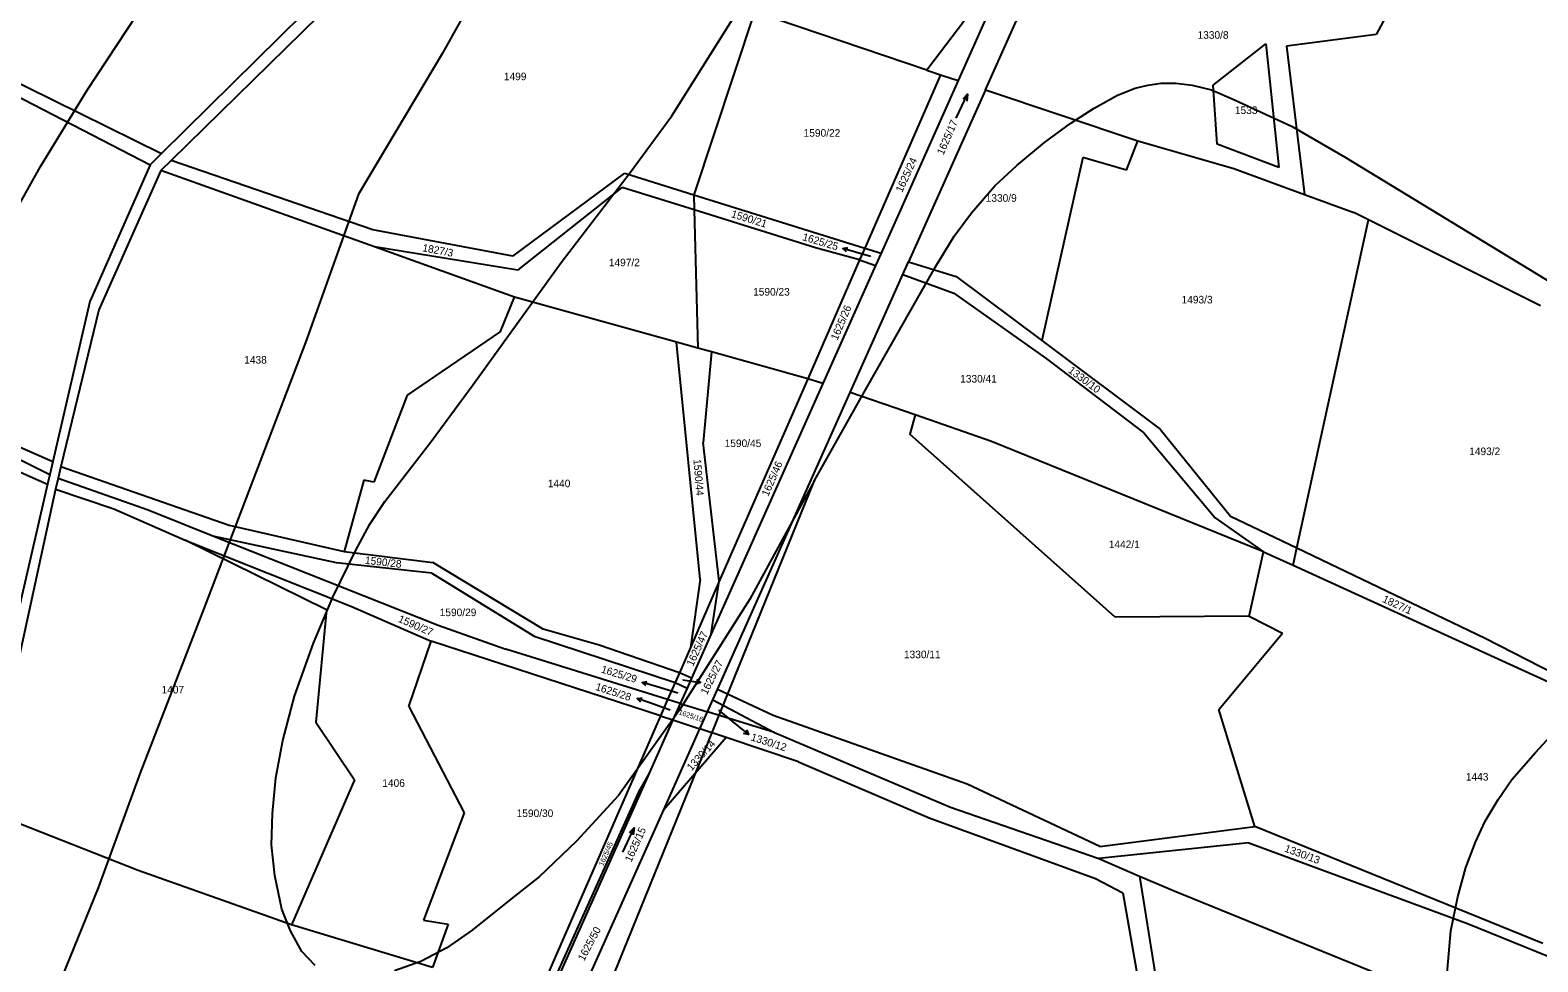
# Model space of a CAD drawing. Extents: x -546762 to -540209, y -1046851 to -1035694.
# Drawn here: x -543306.6 to -542968.6, y -1041200.9 to -1040992 of the extents above; entities that cross this region are included whole.
import ezdxf

# ---------------------------------------------------------------- set-up
doc = ezdxf.new("R2010")
doc.units = 0
for name, color, linetype in [('Vrstva 1', 7, 'Continuous'), ('Vrstva 16', 7, 'Continuous'), ('Vrstva 18', 7, 'Continuous'), ('Vrstva 25', 7, 'Continuous'), ('Vrstva 52', 7, 'Continuous'), ('Vrstva 6', 7, 'Continuous')]:
    doc.layers.add(name, color=color, linetype=linetype)

msp = doc.modelspace()

# ---------------------------------------------------------------- linework, layer by layer
at = {"layer": 'Vrstva 1'}
for points in [[(-543069.18, -1040937.44), (-543098.59, -1041003.36)], [(-543092.45, -1041005.44), (-543063.14, -1040939.88)], [(-543092.78, -1040984.15), (-543105.62, -1041000.99)], [(-543102.54, -1041002.03), (-543119.51, -1041040.89)], [(-543105.62, -1041000.99), (-543102.54, -1041002.03)], [(-543098.59, -1041003.36), (-543115.84, -1041042.03)], [(-543092.45, -1041005.44), (-543109.67, -1041043.95)], [(-543120.68, -1041043.57), (-543132.3, -1041070.19)], [(-543119.51, -1041040.89), (-543120.68, -1041043.57)], [(-543115.84, -1041042.03), (-543117.07, -1041044.78)], [(-543117.07, -1041044.78), (-543128.89, -1041071.29)], [(-543122.77, -1041073.26), (-543110.95, -1041046.82)], [(-543110.95, -1041046.82), (-543109.67, -1041043.95)], [(-543132.3, -1041070.19), (-543152.12, -1041115.59)], [(-543128.89, -1041071.29), (-543153.91, -1041127.39)], [(-543152.54, -1041139.88), (-543122.77, -1041073.26)], [(-543152.12, -1041115.59), (-543158.6, -1041130.42)], [(-543153.91, -1041127.39), (-543158.34, -1041137.32)], [(-543158.6, -1041130.42), (-543161.08, -1041136.11)], [(-543161.08, -1041136.11), (-543162.04, -1041138.3)], [(-543158.34, -1041137.32), (-543159.34, -1041139.55)], [(-543162.04, -1041138.3), (-543163.7, -1041142.11)], [(-543159.34, -1041139.55), (-543160.87, -1041142.99)], [(-543153.58, -1041142.21), (-543152.54, -1041139.88)], [(-543163.7, -1041142.11), (-543165.29, -1041145.76)], [(-543160.87, -1041142.99), (-543162.52, -1041146.69)], [(-543160.87, -1041142.99), (-543154.77, -1041144.88)], [(-543156.48, -1041148.71), (-543154.77, -1041144.88)], [(-543154.77, -1041144.88), (-543153.58, -1041142.21)], [(-543165.29, -1041145.76), (-543193.04, -1041209.32)], [(-543162.52, -1041146.69), (-543167.84, -1041158.61)], [(-543162.52, -1041146.69), (-543156.48, -1041148.71)], [(-543164.59, -1041166.87), (-543156.48, -1041148.71)], [(-543167.84, -1041158.61), (-543190.89, -1041210.3)], [(-543184.13, -1041210.58), (-543164.59, -1041166.87)]]:
    msp.add_lwpolyline(points, dxfattribs=at)
at = {"layer": 'Vrstva 16'}
for p, q in [((-543121.55, -1041041.83), (-543124.43, -1041040.99)), ((-543166.52, -1041139.15), (-543169.39, -1041138.28)), ((-543159.31, -1041137.88), (-543156.34, -1041138.28)), ((-543167.7, -1041142.88), (-543170.53, -1041141.89)), ((-543147.9, -1041148.06), (-543145.57, -1041149.95))]:
    msp.add_line(p, q, dxfattribs=at)
for points in [[(-543123.61, -1041041.75), (-543124.43, -1041040.99), (-543123.33, -1041040.79)], [(-543118.23, -1041042.8), (-543121.55, -1041041.83)], [(-543168.58, -1041139.05), (-543169.39, -1041138.28), (-543168.29, -1041138.09)], [(-543160.31, -1041137.74), (-543159.31, -1041137.88)], [(-543157.26, -1041137.65), (-543156.34, -1041138.28), (-543157.4, -1041138.64)], [(-543161.45, -1041140.69), (-543166.52, -1041139.15)], [(-543169.75, -1041142.69), (-543170.53, -1041141.89), (-543169.42, -1041141.75)], [(-543163.13, -1041144.48), (-543167.7, -1041142.88)], [(-543152.31, -1041144.48), (-543147.9, -1041148.06)], [(-543146.03, -1041148.93), (-543145.57, -1041149.95), (-543146.66, -1041149.71)]]:
    msp.add_lwpolyline(points, dxfattribs=at)
at = {"layer": 'Vrstva 25'}
for points in [[(-543099.02, -1041011.8), (-543096.46, -1041006.36), (-543097.55, -1041007.51)], [(-543096.46, -1041006.36), (-543096.65, -1041007.94)], [(-543173.72, -1041176.33), (-543171.24, -1041170.87), (-543172.31, -1041172.03)], [(-543171.24, -1041170.87), (-543171.4, -1041172.44)]]:
    msp.add_lwpolyline(points, dxfattribs=at)
at = {"layer": 'Vrstva 52'}
for points in [[(-543114.91, -1040780.64), (-543113, -1040792.52), (-543112.57, -1040803.33), (-543112.79, -1040813.08), (-543114.48, -1040823.69), (-543117.02, -1040834.08), (-543121.05, -1040844.04), (-543127.62, -1040856.34), (-543132.71, -1040864.4), (-543140.55, -1040877.5), (-543166.14, -1040918.69), (-543197.89, -1040967.9), (-543214.21, -1040997.22), (-543233.03, -1041028.81), (-543244.9, -1041062.1), (-543267.79, -1041121.9), (-543281.99, -1041158.59), (-543291.42, -1041184.35), (-543299.54, -1041204.34), (-543308.14, -1041219.86)], [(-543322.15, -1041054.55), (-543304.35, -1041022.63), (-543293.87, -1041005.52), (-543253.63, -1040944.47), (-543217.93, -1040882.13), (-543193.27, -1040831.47), (-543168.15, -1040787.72)], [(-543242.71, -1041201.78), (-543245.74, -1041198.58), (-543248.28, -1041193.97), (-543250.22, -1041189.12), (-543251.79, -1041181.61), (-543252.52, -1041174.7), (-543252.28, -1041167.68), (-543251.55, -1041159.68), (-543249.97, -1041151.32), (-543247.35, -1041141.35), (-543243.11, -1041129.48), (-543238.75, -1041119.18), (-543233.66, -1041108.76), (-543230.51, -1041102.82), (-543227.12, -1041097.73), (-543216.74, -1041084.25), (-543207.31, -1041071.47), (-543187.6, -1041044.12), (-543172.13, -1041023.97), (-543162.8, -1041011.25), (-543101.67, -1040914.04)], [(-543130.8, -1041093.03), (-543119.35, -1041072.67), (-543103.67, -1041045.1), (-543099.43, -1041038.23), (-543095.55, -1041033.02), (-543090.35, -1041026.96), (-543085.38, -1041022.35), (-543079.2, -1041017.26), (-543073.27, -1041012.9), (-543068.06, -1041009.51), (-543062.86, -1041006.6), (-543058.86, -1041005.08), (-543056.02, -1041004.38), (-543053.05, -1041003.9), (-543049.79, -1041003.9), (-543046.13, -1041004.38)], [(-543046.13, -1041004.38), (-543041.77, -1041005.42), (-543036.64, -1041007.64), (-543023.7, -1041013.66), (-543011.94, -1041020.45), (-542939.35, -1041064.58)], [(-543367.43, -1041496.06), (-543358.52, -1041484.25), (-543291.66, -1041388.79), (-543235.84, -1041305.67), (-543212.48, -1041277.09), (-543186.52, -1041230.33), (-543130.8, -1041093.03)], [(-543130.8, -1041093.03), (-543145.27, -1041119.62), (-543161.13, -1041144.58), (-543174.7, -1041163.61), (-543184.14, -1041173.91), (-543192.53, -1041181.84), (-543198.49, -1041186.61), (-543207.55, -1041193.82), (-543213.23, -1041197.83), (-543219.04, -1041200.88), (-543224.92, -1041202.96)], [(-542956.93, -1041259.59), (-542974.13, -1041243.84), (-542981.46, -1041235.66), (-542985.09, -1041229.36), (-542987.51, -1041223.18), (-542988.84, -1041217.12), (-542989.21, -1041210.21), (-542988.84, -1041202.58), (-542988.12, -1041193.98), (-542986.54, -1041186.34), (-542984.73, -1041179.8), (-542982.55, -1041174.11), (-542980.37, -1041169.38), (-542977.46, -1041164.53), (-542974.43, -1041160.05), (-542969.1, -1041153.99), (-542964.14, -1041148.54)]]:
    msp.add_lwpolyline(points, dxfattribs=at)
at = {"layer": 'Vrstva 6'}
for points in [[(-543218.98, -1040962.2), (-543277.16, -1041019.66)], [(-543216.26, -1040963.63), (-543275.01, -1041021.25)], [(-542995.48, -1040975.63), (-543004.84, -1040993.04)], [(-543144.2, -1040987.96), (-543157.86, -1041028.95)], [(-543105.62, -1041000.99), (-543144.2, -1040987.96)], [(-543041.39, -1041004.41), (-543029.59, -1040995.11)], [(-543029.59, -1040995.11), (-543026.68, -1041022.85)], [(-543004.84, -1040993.04), (-543024.91, -1040995.62)], [(-543024.91, -1040995.62), (-543020.9, -1041028.86)], [(-543313.56, -1041001.76), (-543277.16, -1041019.66)], [(-543102.54, -1041002.03), (-543098.59, -1041003.36)], [(-543316.78, -1041003.12), (-543279.73, -1041022.2)], [(-543092.45, -1041005.44), (-543058.28, -1041016.82)], [(-543040.52, -1041017.59), (-543041.39, -1041004.41)], [(-543277.16, -1041019.66), (-543279.73, -1041022.2)], [(-543060.81, -1041023.41), (-543058.28, -1041016.82)], [(-543058.28, -1041016.82), (-543036.78, -1041023.06)], [(-543026.68, -1041022.85), (-543040.52, -1041017.59)], [(-543279.73, -1041022.2), (-543293.27, -1041052.9)], [(-543275.01, -1041021.25), (-543277.31, -1041023.51)], [(-543229.84, -1041036.82), (-543275.01, -1041021.25)], [(-543070.58, -1041020.61), (-543079.84, -1041061.62)], [(-543060.81, -1041023.41), (-543070.58, -1041020.61)], [(-543036.78, -1041023.06), (-543020.9, -1041028.86)], [(-543277.31, -1041023.51), (-543291.23, -1041054.72)], [(-543229.42, -1041040.65), (-543277.31, -1041023.51)], [(-543198.43, -1041042.68), (-543173.3, -1041024.14)], [(-543173.3, -1041024.14), (-543157.86, -1041028.95)], [(-543197.32, -1041045.83), (-543173.92, -1041027.33)], [(-543157.77, -1041032.36), (-543173.92, -1041027.33)], [(-543157.86, -1041028.95), (-543119.51, -1041040.89)], [(-543157.86, -1041028.95), (-543157.77, -1041032.36)], [(-543020.9, -1041028.86), (-543009.82, -1041032.91)], [(-543130.58, -1041040.84), (-543157.77, -1041032.36)], [(-543157.77, -1041032.36), (-543156.96, -1041063.32)], [(-543006.53, -1041034.56), (-543009.82, -1041032.91)], [(-543198.43, -1041042.68), (-543229.84, -1041036.82)], [(-543022.63, -1041108.14), (-543006.53, -1041034.56)], [(-542968.01, -1041053.85), (-543006.53, -1041034.56)], [(-543197.32, -1041045.83), (-543229.42, -1041040.65)], [(-543198.07, -1041051.87), (-543229.42, -1041040.65)], [(-543120.68, -1041043.57), (-543130.58, -1041040.84)], [(-543120.68, -1041043.57), (-543117.07, -1041044.78)], [(-543119.51, -1041040.89), (-543115.84, -1041042.03)], [(-543110.95, -1041046.82), (-543099.57, -1041051.02)], [(-543109.67, -1041043.95), (-543099.04, -1041047.26)], [(-543099.04, -1041047.26), (-543079.84, -1041061.62)], [(-543293.27, -1041052.9), (-543301.55, -1041088.72)], [(-543201.21, -1041059.59), (-543198.07, -1041051.87)], [(-543161.73, -1041061.99), (-543198.07, -1041051.87)], [(-543099.57, -1041051.02), (-543078.82, -1041065.68)], [(-543291.23, -1041054.72), (-543299.74, -1041089.88)], [(-543201.21, -1041059.59), (-543222.13, -1041073.87)], [(-543156.96, -1041063.32), (-543161.73, -1041061.99)], [(-543156.42, -1041115.22), (-543161.73, -1041061.99)], [(-543153.88, -1041064.18), (-543156.96, -1041063.32)], [(-543079.84, -1041061.62), (-543053.24, -1041081.52)], [(-543153.88, -1041064.18), (-543155.71, -1041084.48)], [(-543132.3, -1041070.19), (-543153.88, -1041064.18)], [(-543078.82, -1041065.68), (-543056.96, -1041082.3)], [(-543128.89, -1041071.29), (-543132.3, -1041070.19)], [(-543222.13, -1041073.87), (-543229.57, -1041093.42)], [(-543108.24, -1041078.31), (-543122.77, -1041073.26)], [(-543333.32, -1041080.3), (-543302.74, -1041093.86)], [(-543108.24, -1041078.31), (-543109.42, -1041082.59)], [(-543091.12, -1041084.26), (-543108.24, -1041078.31)], [(-543320.16, -1041082.74), (-543302.24, -1041091.7)], [(-543315.88, -1041082.44), (-543301.55, -1041088.72)], [(-543063.35, -1041123.65), (-543109.42, -1041082.59)], [(-543056.96, -1041082.3), (-543040.91, -1041101.42)], [(-543053.24, -1041081.52), (-543037.48, -1041101.03)], [(-543152.12, -1041115.59), (-543155.71, -1041084.48)], [(-543030.08, -1041108.99), (-543091.12, -1041084.26)], [(-543301.55, -1041088.72), (-543302.24, -1041091.7)], [(-543299.74, -1041089.88), (-543300.38, -1041092.51)], [(-543299.74, -1041089.88), (-543262.03, -1041103)], [(-543302.74, -1041093.86), (-543319.4, -1041166)], [(-543302.24, -1041091.7), (-543302.74, -1041093.86)], [(-543300.38, -1041092.51), (-543300.97, -1041094.95)], [(-543300.38, -1041092.51), (-543280.19, -1041099.62)], [(-543231.86, -1041092.94), (-543236.22, -1041108.93)], [(-543229.57, -1041093.42), (-543231.86, -1041092.94)], [(-543300.97, -1041094.95), (-543316.64, -1041167.03)], [(-543300.97, -1041094.95), (-543287.86, -1041099.37)], [(-543287.86, -1041099.37), (-543271.9, -1041106.42)], [(-543280.19, -1041099.62), (-543265.31, -1041105.54)], [(-543037.48, -1041101.03), (-543022.63, -1041108.14)], [(-543262.03, -1041103), (-543236.22, -1041108.93)], [(-543040.91, -1041101.42), (-543030.08, -1041108.99)], [(-543271.9, -1041106.42), (-543234.77, -1041121.19)], [(-543240.23, -1041121.98), (-543271.9, -1041106.42)], [(-543265.31, -1041105.54), (-543215.19, -1041125.46)], [(-543237.98, -1041111.45), (-543265.31, -1041105.54)], [(-543236.22, -1041108.93), (-543216.34, -1041111.38)], [(-543033.34, -1041123.44), (-543030.08, -1041108.99)], [(-543030.08, -1041108.99), (-543023.47, -1041112.01)], [(-543023.47, -1041112.01), (-543022.63, -1041108.14)], [(-543022.63, -1041108.14), (-542980.42, -1041128.34)], [(-543216.57, -1041113.79), (-543237.98, -1041111.45)], [(-543216.57, -1041113.79), (-543193.62, -1041127.95)], [(-543191.65, -1041126.38), (-543216.34, -1041111.38)], [(-543023.47, -1041112.01), (-542960.13, -1041140.93)], [(-543156.42, -1041115.22), (-543158.6, -1041130.42)], [(-543153.91, -1041127.39), (-543152.12, -1041115.59)], [(-543234.77, -1041121.19), (-543216.73, -1041129.07)], [(-543240.23, -1041121.98), (-543242.61, -1041147.19)], [(-543033.34, -1041123.44), (-543063.35, -1041123.65)], [(-543033.34, -1041123.44), (-543025.86, -1041127.26)], [(-543215.19, -1041125.46), (-543200, -1041130.86)], [(-543193.62, -1041127.95), (-543162.04, -1041138.3)], [(-543179.04, -1041129.96), (-543191.65, -1041126.38)], [(-543040.14, -1041144.38), (-543025.86, -1041127.26)], [(-543221.72, -1041143.67), (-543216.73, -1041129.07)], [(-543165.29, -1041145.76), (-543216.73, -1041129.07)], [(-543163.7, -1041142.11), (-543200, -1041130.86)], [(-543161.08, -1041136.11), (-543179.04, -1041129.96)], [(-542980.42, -1041128.34), (-542955.45, -1041141.18)], [(-543158.34, -1041137.32), (-543161.08, -1041136.11)], [(-543162.04, -1041138.3), (-543159.34, -1041139.55)], [(-543140.05, -1041145.67), (-543152.54, -1041139.88)], [(-543221.72, -1041143.67), (-543209.34, -1041167.5)], [(-543160.87, -1041142.99), (-543163.7, -1041142.11)], [(-543139.76, -1041149.53), (-543154.77, -1041144.88)], [(-543153.58, -1041142.21), (-543139.76, -1041149.53)], [(-543032.07, -1041170.61), (-543040.14, -1041144.38)], [(-543242.61, -1041147.19), (-543233.92, -1041160.09)], [(-543165.29, -1041145.76), (-543162.52, -1041146.69)], [(-543096.55, -1041161.08), (-543140.05, -1041145.67)], [(-543150.61, -1041150.67), (-543164.59, -1041166.87)], [(-543150.61, -1041150.67), (-543156.48, -1041148.71)], [(-543134.39, -1041156.1), (-543150.61, -1041150.67)], [(-543139.76, -1041149.53), (-543100.27, -1041166.28)], [(-543134.39, -1041156.1), (-543105.09, -1041168.61)], [(-543233.92, -1041160.09), (-543248.03, -1041192.61)], [(-543167.84, -1041158.61), (-543169.83, -1041162.2)], [(-543066.8, -1041175.11), (-543096.55, -1041161.08)], [(-543191.39, -1041210.07), (-543169.83, -1041162.2)], [(-543282.45, -1041180.49), (-543316.64, -1041167.03)], [(-543209.34, -1041167.5), (-543218.42, -1041191.58)], [(-543105.09, -1041168.61), (-543067.76, -1041182.24)], [(-543100.27, -1041166.28), (-543067.02, -1041177.8)], [(-543066.8, -1041175.11), (-543032.07, -1041170.61)], [(-542967.46, -1041196.84), (-543032.07, -1041170.61)], [(-543033.42, -1041174.28), (-543067.02, -1041177.8)], [(-543033.42, -1041174.28), (-542984.39, -1041192.33)], [(-543067.02, -1041177.8), (-543057.87, -1041181.7)], [(-543248.03, -1041192.61), (-543282.45, -1041180.49)], [(-543057.87, -1041181.7), (-543050.12, -1041185)], [(-543057.87, -1041181.7), (-543052.08, -1041218.19)], [(-543067.76, -1041182.24), (-543061.66, -1041185.46)], [(-543061.66, -1041185.46), (-543055.83, -1041218.69)], [(-543050.12, -1041185), (-543004.26, -1041203.7)], [(-543218.42, -1041191.58), (-543212.88, -1041192.49)], [(-542984.39, -1041192.33), (-542966.48, -1041199.59)], [(-543216.44, -1041202.21), (-543248.03, -1041192.61)], [(-543212.88, -1041192.49), (-543216.44, -1041202.21)]]:
    msp.add_lwpolyline(points, dxfattribs=at)

# ---------------------------------------------------------------- texts
at = {"layer": 'Vrstva 16'}
for s, rotation, p in [('1625/25', 343.5034, (-543133.62, -1041039.1)), ('1625/29', 343.3387, (-543178.76, -1041136.06)), ('1625/27', 63.2768, (-543154.9, -1041141.19)), ('1625/28', 342.0347, (-543180.04, -1041139.94)), ('1330/12', 342.1922, (-543145.19, -1041151.24)), ('1625/50', 61.7585, (-543182.46, -1041200.9))]:
    msp.add_text(s, height=1.7, rotation=rotation, dxfattribs=at).set_placement(p)
at = {"layer": 'Vrstva 18'}
for s, height, p in [('1330/8', 1.7, (-543044.89, -1040993.97)), ('1499', 1.7, (-543200.42, -1041003.26)), ('1533', 1.7, (-543036.51, -1041010.85)), ('1590/22', 1.7, (-543133.21, -1041015.93)), ('1330/9', 1.7, (-543092.39, -1041030.52)), ('1497/2', 1.7, (-543176.89, -1041044.99)), ('1625/25', 0.1, (-543118.48, -1041042.8)), ('1590/23', 1.7, (-543144.54, -1041051.55)), ('1493/3', 1.7, (-543048.47, -1041053.31)), ('1438', 1.7, (-543258.64, -1041066.81)), ('1330/41', 1.7, (-543098.11, -1041071.05)), ('1590/45', 1.7, (-543150.92, -1041085.52)), ('1493/2', 1.7, (-542983.98, -1041087.32)), ('1440', 1.7, (-543190.57, -1041094.52)), ('1442/1', 1.7, (-543064.8, -1041108.18)), ('1590/29', 1.7, (-543214.81, -1041123.43)), ('1330/11', 1.7, (-543110.72, -1041132.86)), ('1625/27', 0.1, (-543160.56, -1041137.74)), ('1407', 1.7, (-543277.18, -1041140.76)), ('1625/29', 0.1, (-543161.7, -1041140.69)), ('1625/28', 0.1, (-543163.38, -1041144.48)), ('1330/12', 0.1, (-543152.55, -1041144.48)), ('1443', 1.7, (-542984.73, -1041160.29)), ('1406', 1.7, (-543227.68, -1041161.7)), ('1590/30', 1.7, (-543197.56, -1041168.47))]:
    msp.add_text(s, height=height, dxfattribs=at).set_placement(p)
for s, height, rotation, p in [('1625/17', 1.7, 66.5647, (-543101.87, -1041020.16)), ('1625/24', 1.7, 65.4175, (-543111.13, -1041028.57)), ('1590/21', 1.7, 342.9428, (-543149.6, -1041033.94)), ('1827/3', 1.7, 349.4771, (-543218.79, -1041041.6)), ('1625/26', 1.7, 66.9603, (-543125.65, -1041061.72)), ('1330/10', 1.7, 323.2402, (-543074.04, -1041068.64)), ('1590/44', 1.7, 274.5752, (-543157.93, -1041088.29)), ('1625/46', 1.7, 66.3276, (-543141.16, -1041096.7)), ('1590/28', 1.7, 353.6634, (-543231.64, -1041111.7)), ('1827/1', 1.7, 335.2766, (-543003.6, -1041120.18)), ('1590/27', 1.7, 336.4808, (-543224.28, -1041124.65)), ('1625/47', 1.7, 65.4953, (-543158.02, -1041134.82)), ('1625/16', 1.14, 341.9052, (-543161.36, -1041145.42)), ('1330/14', 1.7, 48.1555, (-543158.34, -1041158.24)), ('1625/15', 1.7, 65.8286, (-543171.85, -1041178.73)), ('1625/45', 1.14, 66.765, (-543178.18, -1041179.55)), ('1330/13', 1.7, 339.6827, (-543025.54, -1041176.17))]:
    msp.add_text(s, height=height, rotation=rotation, dxfattribs=at).set_placement(p)

doc.saveas('drawing.dxf')
